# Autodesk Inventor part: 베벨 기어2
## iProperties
Created: 2012-07
Part Number: 베벨 기어2
Material: Steel, Mild
Document SubType Name: Modeling
Designer: SeoGD™ [www.esajin.kr]
Categories: <?xml version="1.0" encoding="UTF-16"?> <MemberInstance><Categories><FamilyTemplate><FamilyTemplateParameter ValueType="xs:double" Id="1" ObjectReferenceKey="da
Mass: 60.9118 g
Surface Area: 34.3074 cm^2
Volume: 7.7496 cm^3
Density: 7.86 g/cm^3
CustomPartVersion: 1
Author: SeoGD™ [www.esajin.kr]
